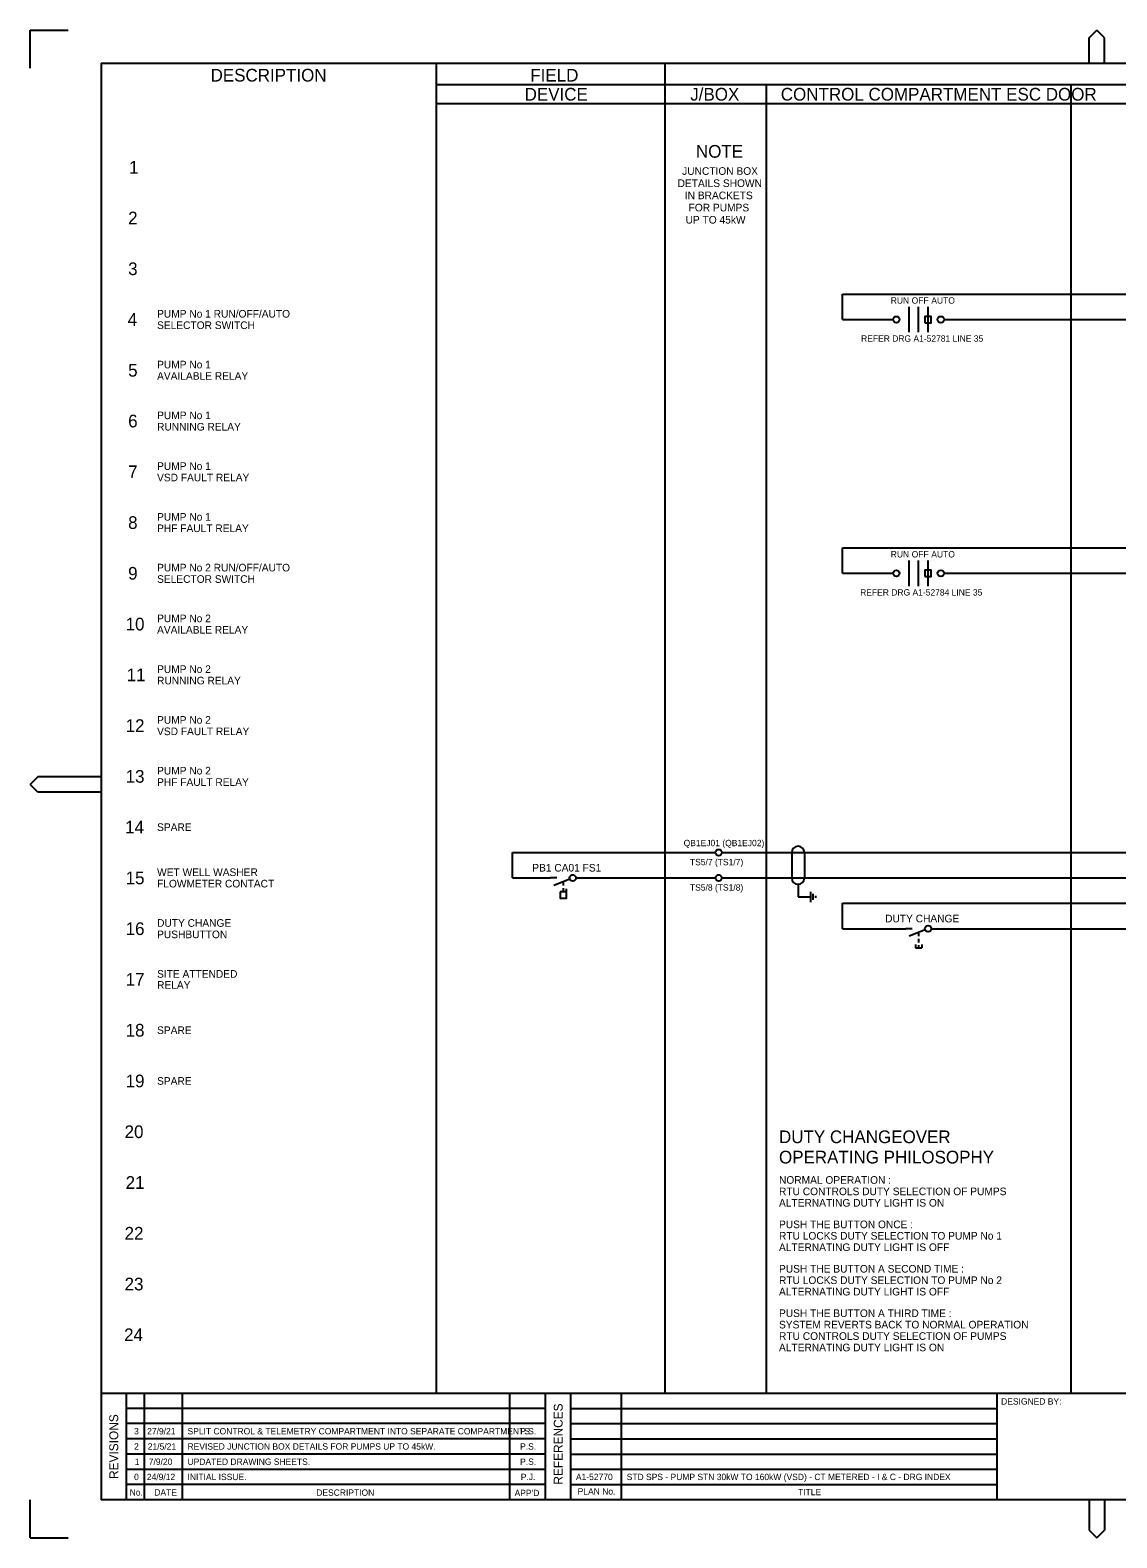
# Model space of a CAD drawing. Extents: x 0 to 841, y 0 to 594.
# Drawn here: x 0 to 428, y 0 to 594 of the extents above; entities that cross this region are included whole.
import ezdxf

# ---------------------------------------------------------------- set-up
doc = ezdxf.new("R2010")
doc.units = 0
for name, color, linetype in [('A1BORDER', 7, 'Continuous'), ('Level 1', 7, 'Continuous'), ('Level 10', 7, 'Continuous'), ('Level 5', 7, 'Continuous')]:
    doc.layers.add(name, color=color, linetype=linetype)

msp = doc.modelspace()

# ---------------------------------------------------------------- linework, layer by layer
at = {"layer": 'A1BORDER'}
for p, q in [((0, 594), (15, 594)), ((0, 579), (0, 594)), ((417.19, 591), (420.19, 594)), ((423.19, 591), (420.19, 594)), ((417.19, 581), (417.19, 591)), ((423.19, 581), (423.19, 591)), ((28, 581), (829, 581)), ((28, 581), (28, 15)), ((3, 299.76), (0, 296.76)), ((28, 299.76), (3, 299.76)), ((3, 293.76), (0, 296.76)), ((28, 293.76), (3, 293.76)), ((28, 57), (829, 57)), ((38, 15), (38, 57)), ((45, 15), (45, 57)), ((60, 15), (60, 57)), ((189, 15), (189, 57)), ((203, 15), (203, 57)), ((213, 15), (213, 57)), ((233, 15), (233, 57)), ((381, 15), (381, 57)), ((203, 51), (38, 51)), ((213, 51), (381, 51)), ((203, 45), (38, 45)), ((213, 45), (381, 45)), ((203, 39), (38, 39)), ((213, 39), (381, 39)), ((203, 33), (38, 33)), ((213, 33), (381, 33)), ((38, 27), (203, 27)), ((213, 27), (381, 27)), ((203, 21), (38, 21)), ((213, 21), (381, 21)), ((0, 0), (0, 15)), ((829, 15), (28, 15)), ((417.19, 15), (417.19, 3)), ((423.19, 15), (423.19, 3)), ((0, 0), (15, 0)), ((417.19, 3), (420.19, 0)), ((423.19, 3), (420.19, 0))]:
    msp.add_line(p, q, dxfattribs=at)
at = {"layer": 'Level 1'}
for p, q in [((160, 581), (160, 57)), ((250, 581), (250, 57)), ((829, 572.5), (160, 572.5)), ((290, 572.5), (290, 57)), ((410, 572.5), (410, 57)), ((829, 565), (160, 565)), ((320, 480), (320, 490)), ((320, 490), (510, 490)), ((346.25, 475), (346.25, 485)), ((350, 475), (350, 485)), ((353.75, 475), (353.75, 485)), ((320, 480), (340, 480)), ((360, 480), (510, 480)), ((320, 380), (320, 390)), ((320, 390), (510, 390)), ((346.25, 375), (346.25, 385)), ((350, 375), (350, 385)), ((353.75, 375), (353.75, 385)), ((320, 380), (340, 380)), ((360, 380), (510, 380)), ((190, 260), (190, 270)), ((190, 270), (270, 270)), ((270, 270), (270, 270)), ((272.5, 270), (272.5, 270)), ((272.5, 270), (608.75, 270)), ((300, 270), (300, 260)), ((305, 270), (305, 260)), ((190, 260), (205, 260)), ((207.5, 260), (205, 260)), ((205, 260), (205, 260)), ((215, 260), (215, 260)), ((215, 260), (270, 260)), ((270, 260), (270, 260)), ((272.5, 260), (272.5, 260)), ((272.5, 260), (690, 260)), ((302.5, 257.5), (302.5, 252.5)), ((302.5, 252.5), (307.5, 252.5)), ((320, 240), (320, 250)), ((320, 250), (608.75, 250)), ((320, 240), (345, 240)), ((347.5, 240), (345, 240)), ((345, 240), (345, 240)), ((355, 240), (355, 240)), ((355, 240), (690, 240))]:
    msp.add_line(p, q, dxfattribs=at)
for points in [[(352.5, 478.75), (355, 478.75), (355, 481.25), (352.5, 481.25)], [(352.5, 378.75), (355, 378.75), (355, 381.25), (352.5, 381.25)]]:
    msp.add_lwpolyline(points, close=True, dxfattribs=at)
for centre in [(341.25, 480), (358.75, 480), (341.25, 380), (358.75, 380)]:
    msp.add_circle(centre, 1.25, dxfattribs=at)
for centre, start, end in [((302.5, 270), 0, 180), ((302.5, 260), 180, 0)]:
    msp.add_arc(centre, 2.5, start, end, dxfattribs=at)
at = {"layer": 'Level 10'}
for p, q in [((212.59, 259.54), (206.25, 257)), ((210, 258.5), (210, 257)), ((210, 256), (210, 254.5)), ((211.25, 254.5), (211.25, 255.75)), ((307.5, 250.5), (307.5, 254.5)), ((308.5, 251.3), (308.5, 253.7)), ((309.5, 252.1), (309.5, 252.9)), ((352.59, 239.54), (346.25, 237)), ((350, 238.5), (350, 237)), ((348.75, 233.75), (348.75, 232.5)), ((348.75, 232.5), (351.25, 232.5)), ((350, 236), (350, 234.5)), ((350, 233.5), (350, 232.5)), ((351.25, 233.75), (351.25, 232.5))]:
    msp.add_line(p, q, dxfattribs=at)
msp.add_lwpolyline([(208.75, 254.5), (208.75, 252), (211.25, 252), (211.25, 254.5)], close=True, dxfattribs=at)
for centre in [(271.25, 270), (213.75, 260), (271.25, 260), (353.75, 240)]:
    msp.add_circle(centre, 1.25, dxfattribs=at)

# ---------------------------------------------------------------- texts
at = {"layer": 'A1BORDER'}
for s, p in [('DESIGNED BY:', (382.5, 52.5)), ('No.', (39.21, 16.65)), ('DATE', (48.92, 16.65)), ('DESCRIPTION', (112.71, 16.57)), ("APP'D", (190.85, 16.44)), ('PLAN No.', (215.69, 17.06)), ('TITLE', (302.5, 16.81))]:
    msp.add_text(s, height=2.5, dxfattribs=at).set_placement(p)
for s, p in [('REVISIONS', (34.68, 23.2)), ('REFERENCES', (209.76, 20.96))]:
    msp.add_text(s, height=3.5, rotation=90, dxfattribs=at).set_placement(p)
at = {"layer": 'Level 1'}
for s, height, p in [('DESCRIPTION', 5, (71.08, 573.75)), ('FIELD', 5, (197.03, 573.75)), ('DEVICE', 5, (194.79, 566.25)), ('J/BOX', 5, (260.04, 566.25)), ('CONTROL COMPARTMENT ESC DOOR', 5, (295.71, 566.25)), ('NOTE', 5, (262.28, 543.75)), ('1', 5, (39, 537.5)), ('2', 5, (38.6, 517.5)), ('3', 5, (38.6, 497.5)), ('RUN', 2.5, (339.02, 486.25)), ('OFF', 2.5, (347.26, 486.25)), ('AUTO', 2.5, (355, 486.25)), ('4', 5, (38.4, 477.5)), ('PUMP No 1 RUN/OFF/AUTO', 3, (50, 480.75)), ('SELECTOR SWITCH', 3, (50, 476.25)), ('PUMP No 1', 3, (50, 460.75)), ('5', 5, (38.6, 457.5)), ('AVAILABLE RELAY', 3, (50, 456.25)), ('6', 5, (38.6, 437.5)), ('PUMP No 1', 3, (50, 440.75)), ('RUNNING RELAY', 3, (50, 436.25)), ('7', 5, (38.6, 417.5)), ('PUMP No 1', 3, (50, 420.75)), ('VSD FAULT RELAY', 3, (50, 416.25)), ('8', 5, (38.6, 397.5)), ('PUMP No 1', 3, (50, 400.75)), ('PHF FAULT RELAY', 3, (50, 396.25)), ('RUN', 2.5, (339.02, 386.25)), ('OFF', 2.5, (347.26, 386.25)), ('AUTO', 2.5, (355, 386.25)), ('9', 5, (38.6, 377.5)), ('PUMP No 2 RUN/OFF/AUTO', 3, (50, 380.75)), ('SELECTOR SWITCH', 3, (50, 376.25)), ('10', 5, (37.61, 357.5)), ('PUMP No 2', 3, (50, 360.75)), ('AVAILABLE RELAY', 3, (50, 356.25)), ('11', 5, (38.01, 337.5)), ('PUMP No 2', 3, (50, 340.75)), ('RUNNING RELAY', 3, (50, 336.25)), ('12', 5, (37.61, 317.5)), ('PUMP No 2', 3, (50, 320.75)), ('VSD FAULT RELAY', 3, (50, 316.25)), ('PUMP No 2', 3, (50, 300.75)), ('13', 5, (37.61, 297.5)), ('PHF FAULT RELAY', 3, (50, 296.25)), ('14', 5, (37.41, 277.5)), ('SPARE', 3, (50, 278.5)), ('QB1EJ01 (QB1EJ02)', 2.5, (257.43, 272.5)), ('TS5/7 (TS1/7)', 2.5, (259.92, 265)), ('15', 5, (37.61, 257.5)), ('WET WELL WASHER', 3, (50, 260.75)), ('FLOWMETER CONTACT', 3, (50, 256.25)), ('TS5/8 (TS1/8)', 2.5, (259.92, 255)), ('DUTY CHANGE', 3, (50, 240.75)), ('16', 5, (37.61, 237.5)), ('PUSHBUTTON', 3, (50, 236.25)), ('17', 5, (37.61, 217.5)), ('SITE ATTENDED', 3, (50, 220.67)), ('RELAY', 3, (50, 216.33)), ('18', 5, (37.61, 197.5)), ('SPARE', 3, (50, 198.5)), ('19', 5, (37.61, 177.5)), ('SPARE', 3, (50, 178.5)), ('20', 5, (37.21, 157.5)), ('DUTY CHANGEOVER', 5, (295, 155.5)), ('OPERATING PHILOSOPHY', 5, (295, 147.5)), ('21', 5, (37.61, 137.5)), ('NORMAL OPERATION :', 3, (295, 139.5)), ('RTU CONTROLS DUTY SELECTION OF PUMPS', 3, (295, 135)), ('ALTERNATING DUTY LIGHT IS ON', 3, (295, 130.5)), ('PUSH THE BUTTON ONCE :', 3, (295, 122)), ('22', 5, (37.21, 117.5)), ('RTU LOCKS DUTY SELECTION TO PUMP No 1', 3, (295, 117.5)), ('ALTERNATING DUTY LIGHT IS OFF', 3, (295, 113)), ('PUSH THE BUTTON A SECOND TIME :', 3, (295, 104.5)), ('23', 5, (37.21, 97.5)), ('RTU LOCKS DUTY SELECTION TO PUMP No 2', 3, (295, 100)), ('ALTERNATING DUTY LIGHT IS OFF', 3, (295, 95.5)), ('PUSH THE BUTTON A THIRD TIME :', 3, (295, 87)), ('SYSTEM REVERTS BACK TO NORMAL OPERATION', 3, (295, 82.5)), ('24', 5, (37.01, 77.5)), ('RTU CONTROLS DUTY SELECTION OF PUMPS', 3, (295, 78)), ('ALTERNATING DUTY LIGHT IS ON', 3, (295, 73.5)), ('3', 2.5, (40.94, 40.75)), ('27/9/21', 2.5, (46.09, 40.75)), ('SPLIT CONTROL & TELEMETRY COMPARTMENT INTO SEPARATE COMPARTMENTS.', 2.5, (62, 40.75)), ('P.S.', 2.5, (193.02, 40.75)), ('2', 2.5, (40.94, 34.75)), ('21/5/21', 2.5, (46.34, 34.75)), ('REVISED JUNCTION BOX DETAILS FOR PUMPS UP TO 45kW.', 2.5, (62, 34.75)), ('P.S.', 2.5, (193.02, 34.75)), ('1', 2.5, (41.19, 28.75)), ('7/9/20', 2.5, (46.72, 28.75)), ('UPDATED DRAWING SHEETS.', 2.5, (62, 28.75)), ('P.S.', 2.5, (193.02, 28.75)), ('0', 2.5, (40.94, 22.75)), ('24/9/12', 2.5, (45.97, 22.75)), ('INITIAL ISSUE.', 2.5, (62, 22.75)), ('P.J.', 2.5, (193.26, 22.75)), ('A1-52770', 2.5, (215, 22.75)), ('STD SPS - PUMP STN 30kW TO 160kW (VSD) - CT METERED - I & C - DRG INDEX', 2.5, (235, 22.75))]:
    msp.add_text(s, height=height, dxfattribs=at).set_placement(p)
at = {"layer": 'Level 5'}
for s, height, p in [('DETAILS SHOWN', 3, (255.06, 532.2)), ('JUNCTION BOX', 3, (256.85, 537)), ('IN BRACKETS', 3, (257.9, 527.4)), ('FOR PUMPS', 3, (259.39, 522.6)), ('UP TO 45kW', 3, (258.2, 517.8)), ('REFER DRG A1-52781 LINE 35', 2.5, (327.34, 471.25)), ('REFER DRG A1-52784 LINE 35', 2.5, (326.97, 371.25)), ('DUTY CHANGE', 3, (336.8, 242.5))]:
    msp.add_text(s, height=height, dxfattribs=at).set_placement(p)
msp.add_text('PB1 CA01 FS1', height=3, rotation=360, dxfattribs=at).set_placement((197.8, 262.5))

doc.saveas('drawing.dxf')
